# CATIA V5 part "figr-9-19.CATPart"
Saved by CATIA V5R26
Part number: Part3
Bounding box of the stored display mesh (mm): x -17.259 to 115.9, y -137.259 to 0, z -17.083 to 17.083
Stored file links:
  D:\_Deepak\CATIA\CATIA V5-6R2016_Deepak\Resources\Part files\Partfiles\c09_catia_v5_6r2016_prt\figr-9-19.CATPart
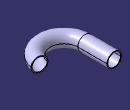
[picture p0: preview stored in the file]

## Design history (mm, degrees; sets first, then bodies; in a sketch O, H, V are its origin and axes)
Body1 (main body)
  Sketch1 on zx-plane, origin (0, 0, 0), H (-1, 0, 0), V (0, 0, 1)
    circle A1 centre (0, 0) radius 17.2586
  Sketch2 on xy-plane, origin (0, 0, 0), H (1, 0, 0), V (0, 1, 0)
    line L1 (0, 0) -> (0, -70)
    arc A1 centre (50, -70) radius 50 from (0, -70) to (50, -120) ccw
    arc A2 centre (50, -70) radius 50 from (50, -120) to (98.9898, -80) ccw
    vertical: L1 V
    tangency: A1 L1, A2 L1, A2 A1
  Rib1: profile Sketch1, centre curve Sketch2, thin wall 2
